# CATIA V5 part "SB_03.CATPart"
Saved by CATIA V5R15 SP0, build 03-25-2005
Part number: SB_03
Material "Green Blue": density 7860 kg/m3, Young's modulus 2e+11 Pa, Poisson ratio 0.266
Bounding box of the stored display mesh (mm): x 0 to 79, y 0 to 237, z 0 to 49.2
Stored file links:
  E:\#01 CATIA Lecture Materials\#06 DMU\#11 DMU Page01 KIN EX11\SB_03.CATPart
  C:\Program Files\Dassault Systemes\B20\win_b64\startup\materials\Catalog.CATMaterial
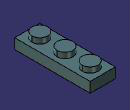
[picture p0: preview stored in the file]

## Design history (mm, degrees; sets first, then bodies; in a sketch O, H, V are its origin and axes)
Body1 (main body), material "Green Blue"
  Sketch1 on xy-plane, origin (0, 0, 0), H (1, 0, 0), V (0, 1, 0)
    circle A1 centre (39.5, 39.5) radius 24.5
    point P1 (39.5, 39.5)
    radius A1 = 24.5
    distance P1 H = 39.5
    distance P1 V = 39.5
  Pad1: profile Sketch1, direction (0, 0, 1), length 49.2
  RectPattern1: of Pad1, direction 1 instances 3, spacing 79, along yz-plane
  Sketch2 on xy-plane, origin (0, 0, 0), H (1, 0, 0), V (0, 1, 0)
    point P1 (0, 237)
    line L1 (0, 237) -> (79, 237)
    line L2 (79, 237) -> (79, 0)
    line L3 (79, 0) -> (0, 0)
    line L4 (0, 0) -> (0, 237)
    point P3 (79, 0)
    distance L2 L4 = 79
    distance L1 L3 = 237 {= RectPattern1.Nb1 * 79mm}
    coincidence: P1 V, P3 H
    horizontal: L1 H, L3 H
    vertical: L2 V, L4 V
  Pad2: profile Sketch2, direction (0, 0, 1), length 32
  Shell1: ExtOffset 0, Face face of Pad2, IntOffset 15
